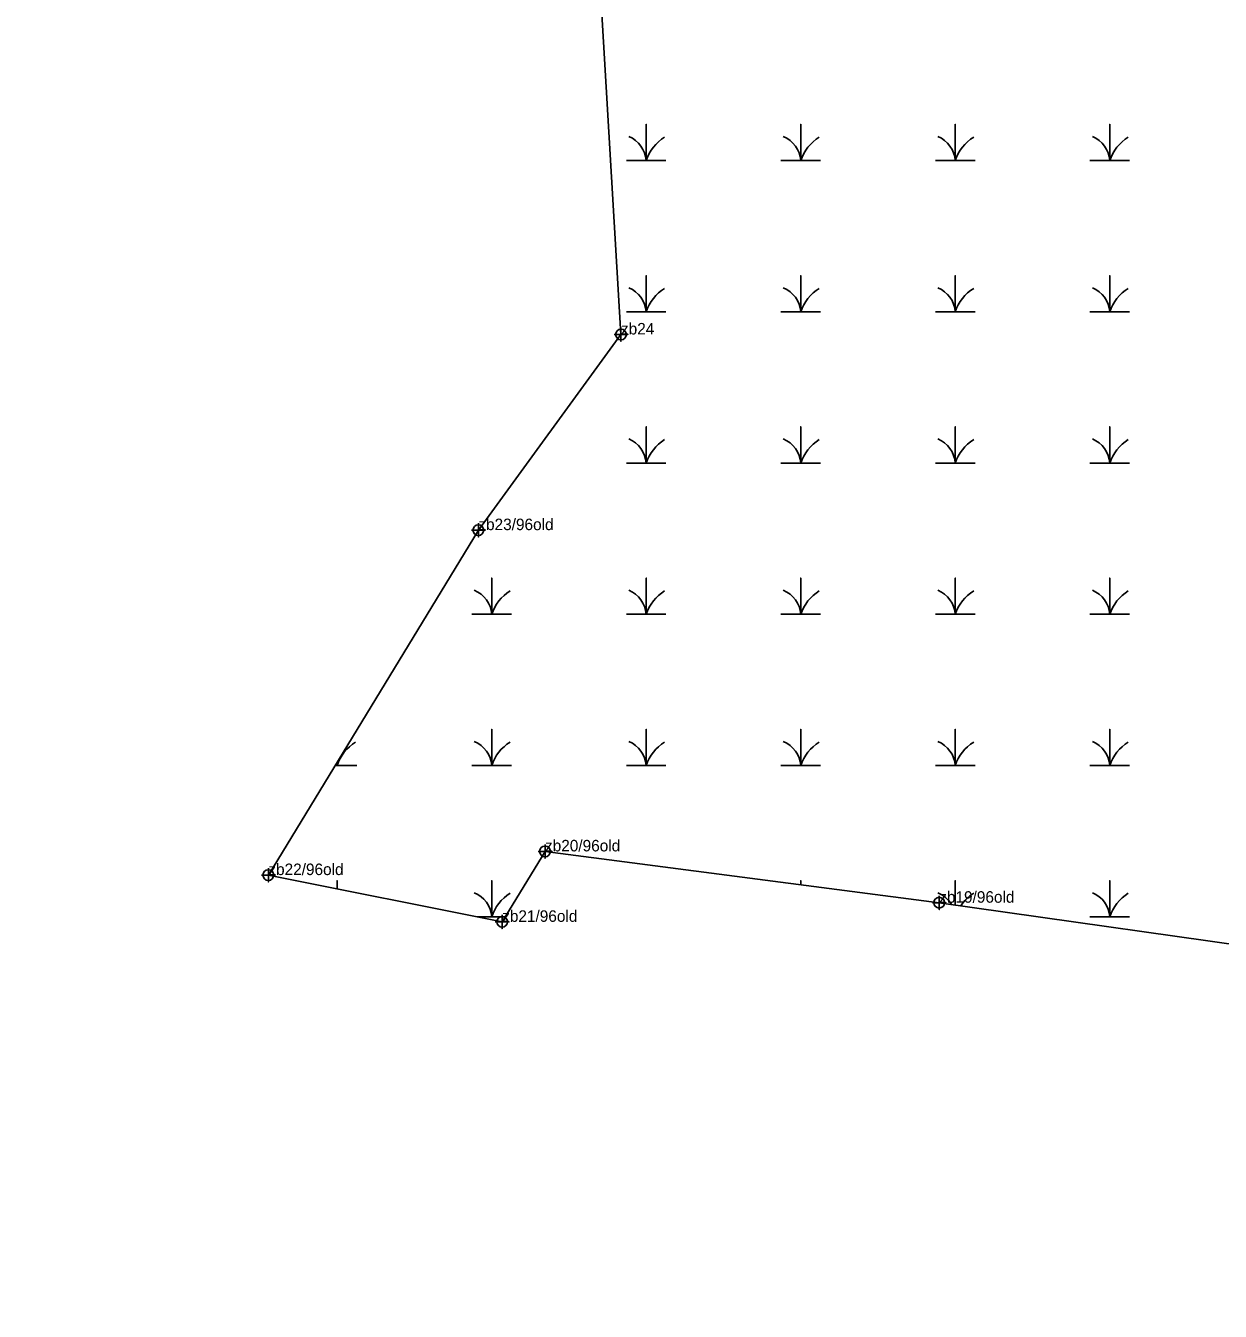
# Model space of a CAD drawing. Extents: x 2071991 to 2268989, y 436479 to 469629.
# Drawn here: x 2251160 to 2251679, y 438675 to 439235 of the extents above; entities that cross this region are included whole.
import ezdxf

# ---------------------------------------------------------------- set-up
doc = ezdxf.new("R2010")
doc.units = 0
for name, color, linetype in [('Exist Environmental Wetland Boundary', 7, 'Continuous'), ('Exist Environmental Wetland Boundary Cogo Comment', 7, 'Continuous'), ('Exist Environmental Wetland Boundary Cogo Point CELL', 7, 'Continuous'), ('Exist Hydro Swamp or Marsh', 7, 'Continuous')]:
    doc.layers.add(name, color=color, linetype=linetype)

msp = doc.modelspace()

# ---------------------------------------------------------------- linework, layer by layer
at = {"layer": 'Exist Environmental Wetland Boundary'}
msp.add_lwpolyline([(2251159.61, 439601.08), (2251261.98, 439510.93), (2251353.72, 439431.67), (2251408.06, 439276.46), (2251418.5, 439100.24), (2251356.47, 439015.14), (2251265.14, 438865.12), (2251366.82, 438844.78), (2251385.46, 438875.42), (2251556.91, 438853.1), (2251718.82, 438830.13), (2251868.44, 438639.97), (2251940.74, 438572.89), (2252098.49, 438426.72), (2252083.03, 438409.31), (2252090.25, 438402.8), (2252096.84, 438411.38), (2252129.61, 438370.68)], dxfattribs=at)
at = {"layer": 'Exist Environmental Wetland Boundary Cogo Point CELL'}
for points in [[(2251418.5, 439103.24), (2251418.5, 439097.24), (2251418.5, 439100.24), (2251421.5, 439100.24), (2251415.5, 439100.24)], [(2251356.47, 439018.14), (2251356.47, 439012.14), (2251356.47, 439015.14), (2251359.47, 439015.14), (2251353.47, 439015.14)], [(2251385.46, 438878.42), (2251385.46, 438872.42), (2251385.46, 438875.42), (2251388.46, 438875.42), (2251382.46, 438875.42)], [(2251265.14, 438868.12), (2251265.14, 438862.12), (2251265.14, 438865.12), (2251268.14, 438865.12), (2251262.14, 438865.12)], [(2251556.91, 438856.1), (2251556.91, 438850.1), (2251556.91, 438853.1), (2251559.91, 438853.1), (2251553.91, 438853.1)], [(2251366.82, 438847.78), (2251366.82, 438841.78), (2251366.82, 438844.78), (2251369.82, 438844.78), (2251363.82, 438844.78)]]:
    msp.add_lwpolyline(points, dxfattribs=at)
for centre in [(2251418.5, 439100.24), (2251356.47, 439015.14), (2251385.46, 438875.42), (2251265.14, 438865.12), (2251556.91, 438853.1), (2251366.82, 438844.78)]:
    msp.add_circle(centre, 2.34, dxfattribs=at)
at = {"layer": 'Exist Hydro Swamp or Marsh'}
for points in [[(2251420.86, 439175.87), (2251429.47, 439175.87), (2251429.47, 439191.65), (2251429.47, 439175.87), (2251438.07, 439175.87)], [(2251488.07, 439175.87), (2251496.67, 439175.87), (2251496.67, 439191.65), (2251496.67, 439175.87), (2251505.27, 439175.87)], [(2251555.27, 439175.87), (2251563.87, 439175.87), (2251563.87, 439191.65), (2251563.87, 439175.87), (2251572.47, 439175.87)], [(2251622.47, 439175.87), (2251631.08, 439175.87), (2251631.08, 439191.65), (2251631.08, 439175.87), (2251639.68, 439175.87)], [(2251420.86, 439110.09), (2251429.47, 439110.09), (2251429.47, 439125.87), (2251429.47, 439110.09), (2251438.07, 439110.09)], [(2251488.07, 439110.09), (2251496.67, 439110.09), (2251496.67, 439125.87), (2251496.67, 439110.09), (2251505.27, 439110.09)], [(2251555.27, 439110.09), (2251563.87, 439110.09), (2251563.87, 439125.87), (2251563.87, 439110.09), (2251572.47, 439110.09)], [(2251622.47, 439110.09), (2251631.08, 439110.09), (2251631.08, 439125.87), (2251631.08, 439110.09), (2251639.68, 439110.09)], [(2251420.86, 439044.31), (2251429.47, 439044.31), (2251429.47, 439060.09), (2251429.47, 439044.31), (2251438.07, 439044.31)], [(2251488.07, 439044.31), (2251496.67, 439044.31), (2251496.67, 439060.09), (2251496.67, 439044.31), (2251505.27, 439044.31)], [(2251555.27, 439044.31), (2251563.87, 439044.31), (2251563.87, 439060.09), (2251563.87, 439044.31), (2251572.47, 439044.31)], [(2251622.47, 439044.31), (2251631.08, 439044.31), (2251631.08, 439060.09), (2251631.08, 439044.31), (2251639.68, 439044.31)], [(2251353.66, 438978.53), (2251362.26, 438978.53), (2251362.26, 438994.31), (2251362.26, 438978.53), (2251370.86, 438978.53)], [(2251420.86, 438978.53), (2251429.47, 438978.53), (2251429.47, 438994.31), (2251429.47, 438978.53), (2251438.07, 438978.53)], [(2251488.07, 438978.53), (2251496.67, 438978.53), (2251496.67, 438994.31), (2251496.67, 438978.53), (2251505.27, 438978.53)], [(2251555.27, 438978.53), (2251563.87, 438978.53), (2251563.87, 438994.31), (2251563.87, 438978.53), (2251572.47, 438978.53)], [(2251622.47, 438978.53), (2251631.08, 438978.53), (2251631.08, 438994.31), (2251631.08, 438978.53), (2251639.68, 438978.53)], [(2251353.66, 438912.75), (2251362.26, 438912.75), (2251362.26, 438928.53), (2251362.26, 438912.75), (2251370.86, 438912.75)], [(2251420.86, 438912.75), (2251429.47, 438912.75), (2251429.47, 438928.53), (2251429.47, 438912.75), (2251438.07, 438912.75)], [(2251488.07, 438912.75), (2251496.67, 438912.75), (2251496.67, 438928.53), (2251496.67, 438912.75), (2251505.27, 438912.75)], [(2251555.27, 438912.75), (2251563.87, 438912.75), (2251563.87, 438928.53), (2251563.87, 438912.75), (2251572.47, 438912.75)], [(2251622.47, 438912.75), (2251631.08, 438912.75), (2251631.08, 438928.53), (2251631.08, 438912.75), (2251639.68, 438912.75)], [(2251294.14, 438912.75), (2251295.06, 438912.75), (2251295.06, 438914.26)], [(2251295.06, 438914.26), (2251295.06, 438912.75), (2251303.66, 438912.75)], [(2251295.06, 438859.13), (2251295.06, 438862.75), (2251295.06, 438859.13)], [(2251355.89, 438846.97), (2251362.26, 438846.97), (2251362.26, 438862.75), (2251362.26, 438846.97), (2251368.15, 438846.97)], [(2251496.67, 438860.94), (2251496.67, 438862.75), (2251496.67, 438860.94)], [(2251563.87, 438852.11), (2251563.87, 438862.75), (2251563.87, 438852.11)], [(2251622.47, 438846.97), (2251631.08, 438846.97), (2251631.08, 438862.75), (2251631.08, 438846.97), (2251639.68, 438846.97)]]:
    msp.add_lwpolyline(points, dxfattribs=at)
for centre, radius, start, end in [((2251417.2, 439174.98), 12.3, 4.1403, 67.535), ((2251447.71, 439169.81), 19.22, 122.1274, 161.6222), ((2251484.4, 439174.98), 12.3, 4.1403, 67.535), ((2251514.91, 439169.81), 19.22, 122.1274, 161.6222), ((2251551.61, 439174.98), 12.3, 4.1403, 67.535), ((2251582.12, 439169.81), 19.22, 122.1274, 161.6222), ((2251618.81, 439174.98), 12.3, 4.1403, 67.535), ((2251649.32, 439169.81), 19.22, 122.1274, 161.6222), ((2251417.2, 439109.2), 12.3, 4.1403, 67.535), ((2251447.71, 439104.03), 19.22, 122.1274, 161.6222), ((2251484.4, 439109.2), 12.3, 4.1403, 67.535), ((2251514.91, 439104.03), 19.22, 122.1274, 161.6222), ((2251551.61, 439109.2), 12.3, 4.1403, 67.535), ((2251582.12, 439104.03), 19.22, 122.1274, 161.6222), ((2251618.81, 439109.2), 12.3, 4.1403, 67.535), ((2251649.32, 439104.03), 19.22, 122.1274, 161.6222), ((2251417.2, 439043.42), 12.3, 4.1403, 67.535), ((2251447.71, 439038.25), 19.22, 122.1274, 161.6222), ((2251484.4, 439043.42), 12.3, 4.1403, 67.535), ((2251514.91, 439038.25), 19.22, 122.1274, 161.6222), ((2251551.61, 439043.42), 12.3, 4.1403, 67.535), ((2251582.12, 439038.25), 19.22, 122.1274, 161.6222), ((2251618.81, 439043.42), 12.3, 4.1403, 67.535), ((2251649.32, 439038.25), 19.22, 122.1274, 161.6222), ((2251350, 438977.64), 12.3, 4.1403, 67.535), ((2251380.51, 438972.47), 19.22, 122.1274, 161.6222), ((2251417.2, 438977.64), 12.3, 4.1403, 67.535), ((2251447.71, 438972.47), 19.22, 122.1274, 161.6222), ((2251484.4, 438977.64), 12.3, 4.1403, 67.535), ((2251514.91, 438972.47), 19.22, 122.1274, 161.6222), ((2251551.61, 438977.64), 12.3, 4.1403, 67.535), ((2251582.12, 438972.47), 19.22, 122.1274, 161.6222), ((2251618.81, 438977.64), 12.3, 4.1403, 67.535), ((2251649.32, 438972.47), 19.22, 122.1274, 161.6222), ((2251313.3, 438906.69), 19.22, 122.1274, 161.6222), ((2251350, 438911.86), 12.3, 4.1403, 67.535), ((2251380.51, 438906.69), 19.22, 122.1274, 161.6222), ((2251417.2, 438911.86), 12.3, 4.1403, 67.535), ((2251447.71, 438906.69), 19.22, 122.1274, 161.6222), ((2251484.4, 438911.86), 12.3, 4.1403, 67.535), ((2251514.91, 438906.69), 19.22, 122.1274, 161.6222), ((2251551.61, 438911.86), 12.3, 4.1403, 67.535), ((2251582.12, 438906.69), 19.22, 122.1274, 161.6222), ((2251618.81, 438911.86), 12.3, 4.1403, 67.535), ((2251649.32, 438906.69), 19.22, 122.1274, 161.6222), ((2251282.79, 438911.86), 12.3, 4.1403, 10.0551), ((2251350, 438846.08), 12.3, 4.1403, 67.535), ((2251380.51, 438840.91), 19.22, 122.1274, 161.6222), ((2251551.61, 438846.08), 12.3, 30.6585, 67.535), ((2251582.12, 438840.91), 19.22, 122.1274, 145.5782), ((2251618.81, 438846.08), 12.3, 4.1403, 67.535), ((2251649.32, 438840.91), 19.22, 122.1274, 161.6222)]:
    msp.add_arc(centre, radius, start, end, dxfattribs=at)

# ---------------------------------------------------------------- texts
at = {"layer": 'Exist Environmental Wetland Boundary Cogo Comment'}
for s, p in [('zb24', (2251418.5, 439100.24)), ('zb23/96old', (2251356.47, 439015.14)), ('zb20/96old', (2251385.46, 438875.42)), ('zb22/96old', (2251265.14, 438865.12)), ('zb19/96old', (2251556.91, 438853.1)), ('zb21/96old', (2251366.82, 438844.78))]:
    msp.add_text(s, height=5, dxfattribs=at).set_placement(p)

doc.saveas('drawing.dxf')
